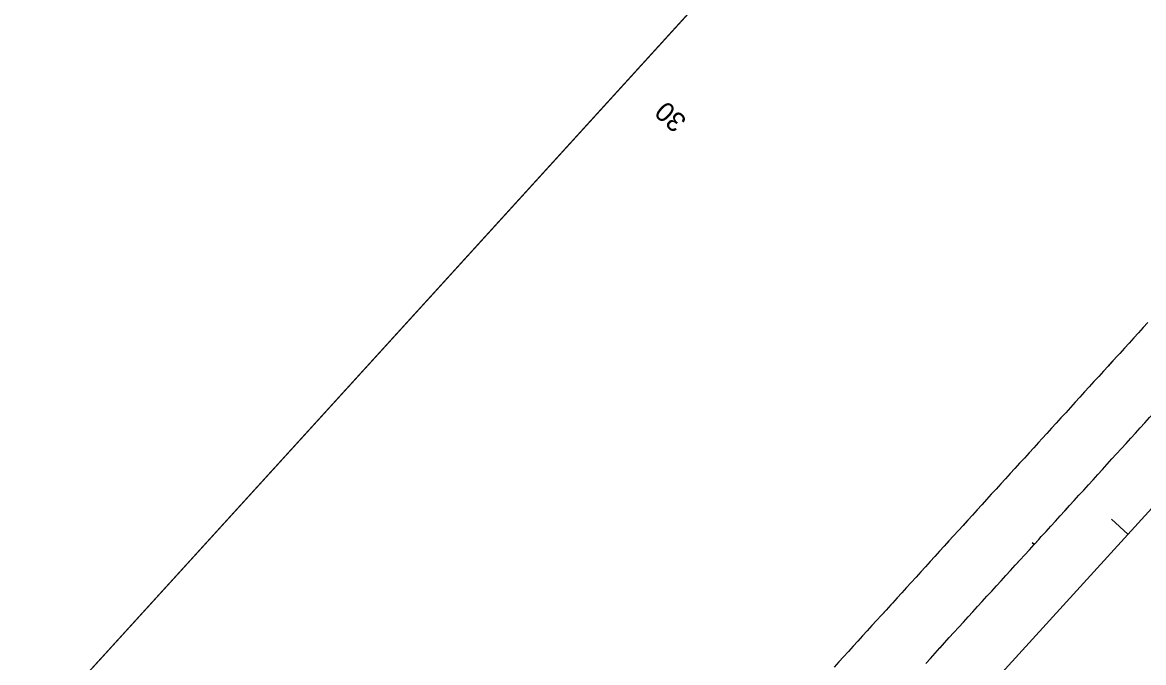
# Model space of a CAD drawing. Extents: x 1807040 to 1808827, y 913493 to 915218.
# Drawn here: x 1807609.2 to 1808009.9, y 914007.6 to 914236.2 of the extents above; entities that cross this region are included whole.
import ezdxf

# ---------------------------------------------------------------- set-up
doc = ezdxf.new("R2010")
doc.units = 0
for name, color, linetype in [('Old_Level_18', 7, 'Continuous'), ('Prop EOT', 7, 'Continuous'), ('Prop Horizontal Alignment Tick Label', 7, 'Continuous'), ('Prop Horizontal Alignment Tick Large', 7, 'Continuous'), ('Scratch_Level_0', 7, 'Continuous'), ('Scratch_Level_1', 7, 'Continuous'), ('Scratch_Level_3', 7, 'Continuous')]:
    doc.layers.add(name, color=color, linetype=linetype)

msp = doc.modelspace()

# ---------------------------------------------------------------- linework, layer by layer
at = {"layer": 'Old_Level_18'}
msp.add_line((1808438.77, 914888.63), (1807428.35, 913780.01), dxfattribs=at)
at = {"layer": 'Prop EOT'}
for points in [[(1808011.43, 914129.13), (1808009.75, 914127.29), (1808008.06, 914125.44), (1808006.38, 914123.59), (1808004.7, 914121.75), (1808003.01, 914119.9), (1808001.33, 914118.05), (1808000.55, 914117.2), (1807998.87, 914115.36), (1807997.18, 914113.51), (1807995.5, 914111.66), (1807993.82, 914109.81), (1807992.13, 914107.96), (1807990.45, 914106.11), (1807988.77, 914104.26), (1807987.08, 914102.42), (1807985.4, 914100.57), (1807983.72, 914098.72), (1807982.04, 914096.87), (1807980.35, 914095.02), (1807978.67, 914093.17), (1807976.99, 914091.32), (1807975.3, 914089.48), (1807973.62, 914087.63), (1807972.3, 914086.18), (1807970.62, 914084.33), (1807968.93, 914082.48), (1807967.25, 914080.64), (1807965.56, 914078.79), (1807963.88, 914076.94), (1807962.19, 914075.1), (1807960.51, 914073.25), (1807958.82, 914071.4), (1807957.14, 914069.56), (1807955.45, 914067.71), (1807953.76, 914065.86), (1807952.08, 914064.01), (1807950.4, 914062.16), (1807948.72, 914060.31), (1807947.04, 914058.46), (1807945.35, 914056.61), (1807943.67, 914054.76), (1807941.99, 914052.91), (1807940.31, 914051.06), (1807938.62, 914049.21), (1807936.94, 914047.36), (1807935.26, 914045.51), (1807933.58, 914043.66), (1807931.9, 914041.81), (1807930.21, 914039.97), (1807928.53, 914038.12), (1807926.85, 914036.27), (1807925.17, 914034.42), (1807923.49, 914032.57), (1807921.8, 914030.72), (1807920.12, 914028.87), (1807919.52, 914028.2), (1807917.83, 914026.35), (1807916.15, 914024.51), (1807914.46, 914022.66), (1807912.78, 914020.81), (1807911.09, 914018.97), (1807909.41, 914017.12), (1807907.72, 914015.27), (1807906.04, 914013.43), (1807904.35, 914011.58), (1807902.66, 914009.73), (1807900.98, 914007.89), (1807899.29, 914006.04)], [(1807931.99, 914007.28), (1807933.68, 914009.13), (1807935.36, 914010.98), (1807937.05, 914012.83), (1807938.73, 914014.67), (1807940.42, 914016.52), (1807942.1, 914018.37), (1807943.79, 914020.21), (1807945.47, 914022.06), (1807947.16, 914023.91), (1807948.84, 914025.76), (1807950.52, 914027.6), (1807952.21, 914029.45), (1807953.89, 914031.3), (1807955.58, 914033.14), (1807957.26, 914034.99), (1807958.95, 914036.84), (1807960.63, 914038.69), (1807962.32, 914040.53), (1807964, 914042.38), (1807965.69, 914044.23), (1807967.37, 914046.08), (1807969.05, 914047.92), (1807970.74, 914049.77), (1807972.42, 914051.62), (1807973.31, 914052.59), (1807975, 914054.44), (1807976.68, 914056.29), (1807978.36, 914058.14), (1807980.04, 914059.99), (1807981.73, 914061.84), (1807983.41, 914063.69), (1807985.09, 914065.54), (1807986.77, 914067.39), (1807988.46, 914069.24), (1807990.14, 914071.08), (1807991.82, 914072.93), (1807993.5, 914074.78), (1807995.19, 914076.63), (1807996.87, 914078.48), (1807998.55, 914080.33), (1808000.23, 914082.18), (1808001.92, 914084.03), (1808003.6, 914085.88), (1808005.28, 914087.73), (1808006.96, 914089.58), (1808008.65, 914091.42), (1808010.33, 914093.27)]]:
    msp.add_lwpolyline(points, dxfattribs=at)
at = {"layer": 'Prop Horizontal Alignment Tick Large'}
msp.add_line((1808004.25, 914053.49), (1807998.34, 914058.88), dxfattribs=at)
at = {"layer": 'Scratch_Level_0'}
for p, q in [((1807995.5, 914111.66), (1807993.82, 914109.81)), ((1807997.18, 914113.51), (1807995.5, 914111.66)), ((1807997.33, 914113.67), (1807997.18, 914113.51)), ((1807992.13, 914107.96), (1807990.45, 914106.11)), ((1807993.82, 914109.81), (1807992.13, 914107.96)), ((1807985.4, 914100.57), (1807983.72, 914098.72)), ((1807987.08, 914102.42), (1807985.4, 914100.57)), ((1807983.72, 914098.72), (1807982.04, 914096.87)), ((1807976.99, 914091.32), (1807975.3, 914089.48)), ((1807978.67, 914093.17), (1807976.99, 914091.32)), ((1807975.3, 914089.48), (1807973.62, 914087.63)), ((1808003.6, 914085.88), (1808005.28, 914087.73)), ((1807970.62, 914084.33), (1807968.93, 914082.48)), ((1807967.25, 914080.64), (1807965.56, 914078.79)), ((1807968.93, 914082.48), (1807967.25, 914080.64)), ((1807996.87, 914078.48), (1807998.55, 914080.33)), ((1807998.55, 914080.33), (1808000.23, 914082.18)), ((1807962.19, 914075.1), (1807960.51, 914073.25)), ((1807963.88, 914076.94), (1807962.19, 914075.1)), ((1807965.56, 914078.79), (1807963.88, 914076.94)), ((1807993.5, 914074.78), (1807995.19, 914076.63)), ((1807995.19, 914076.63), (1807996.87, 914078.48)), ((1807958.82, 914071.4), (1807957.14, 914069.56)), ((1807960.51, 914073.25), (1807958.82, 914071.4)), ((1807988.46, 914069.24), (1807990.14, 914071.08)), ((1807990.14, 914071.08), (1807991.82, 914072.93)), ((1807991.82, 914072.93), (1807993.5, 914074.78)), ((1807957.14, 914069.56), (1807956.95, 914069.35)), ((1807986.77, 914067.39), (1807988.46, 914069.24)), ((1807952.15, 914064.08), (1807952.08, 914064.01)), ((1807953.76, 914065.86), (1807952.15, 914064.08)), ((1807982.03, 914062.17), (1807983.41, 914063.69)), ((1807981.73, 914061.84), (1807982.03, 914062.17)), ((1807943.67, 914054.76), (1807941.99, 914052.91)), ((1807975, 914054.44), (1807976.68, 914056.29)), ((1807976.68, 914056.29), (1807978.36, 914058.14)), ((1807940.31, 914051.06), (1807939.75, 914050.46)), ((1807941.99, 914052.91), (1807940.31, 914051.06)), ((1807971.01, 914050.07), (1807972.42, 914051.62)), ((1807972.42, 914051.62), (1807973.31, 914052.59)), ((1807973.31, 914052.59), (1807975, 914054.44)), ((1807939.75, 914050.46), (1807938.62, 914049.21)), ((1807970.75, 914049.78), (1807970.04, 914050.33)), ((1807970.04, 914050.33), (1807971.01, 914050.07)), ((1807964.48, 914042.91), (1807965.69, 914044.23)), ((1807921.8, 914030.72), (1807920.12, 914028.87)), ((1807919.52, 914028.2), (1807917.83, 914026.35)), ((1807920.12, 914028.87), (1807919.52, 914028.2)), ((1807917.83, 914026.35), (1807916.66, 914025.07)), ((1807911.09, 914018.97), (1807909.57, 914017.31)), ((1807912.78, 914020.81), (1807911.09, 914018.97)), ((1807914.46, 914022.66), (1807912.78, 914020.81)), ((1807943.79, 914020.21), (1807943.86, 914020.3)), ((1807909.57, 914017.31), (1807909.41, 914017.12)), ((1807904.35, 914011.58), (1807902.66, 914009.73)), ((1807937.05, 914012.83), (1807937.13, 914012.91)), ((1807900.98, 914007.89), (1807899.29, 914006.04)), ((1807902.66, 914009.73), (1807900.98, 914007.89)), ((1807931.99, 914007.28), (1807933.68, 914009.13))]:
    msp.add_line(p, q, dxfattribs=at)
for points in [[(1808011.43, 914129.13), (1808009.75, 914127.29), (1808008.06, 914125.44)], [(1808008.06, 914125.44), (1808006.38, 914123.59), (1808004.7, 914121.75), (1808003.01, 914119.9), (1808001.33, 914118.05), (1808000.55, 914117.2)], [(1808000.55, 914117.2), (1807998.87, 914115.36), (1807997.33, 914113.67)], [(1807990.45, 914106.11), (1807988.77, 914104.26), (1807987.08, 914102.42)], [(1807982.04, 914096.87), (1807980.35, 914095.02), (1807978.67, 914093.17)], [(1808008.65, 914091.42), (1808010.33, 914093.27), (1808012.01, 914095.12), (1808013.69, 914096.97)], [(1808005.28, 914087.73), (1808006.96, 914089.58), (1808008.65, 914091.42)], [(1807973.62, 914087.63), (1807972.3, 914086.18), (1807970.62, 914084.33)], [(1808000.23, 914082.18), (1808001.92, 914084.03), (1808003.6, 914085.88)], [(1807956.95, 914069.35), (1807955.45, 914067.71), (1807953.76, 914065.86)], [(1807983.41, 914063.69), (1807985.09, 914065.54), (1807986.77, 914067.39)], [(1807952.08, 914064.01), (1807950.4, 914062.16), (1807948.72, 914060.31)], [(1807948.72, 914060.31), (1807947.04, 914058.46), (1807945.89, 914057.2)], [(1807978.36, 914058.14), (1807980.04, 914059.99), (1807981.73, 914061.84)], [(1807945.89, 914057.2), (1807945.35, 914056.61), (1807943.67, 914054.76)], [(1807938.62, 914049.21), (1807936.94, 914047.36), (1807935.26, 914045.51), (1807933.58, 914043.66)], [(1807965.69, 914044.23), (1807967.37, 914046.08), (1807969.05, 914047.92), (1807970.74, 914049.77), (1807970.75, 914049.78)], [(1807933.58, 914043.66), (1807931.9, 914041.81), (1807930.21, 914039.97), (1807928.53, 914038.12), (1807926.85, 914036.27)], [(1807962.32, 914040.53), (1807964, 914042.38), (1807964.48, 914042.91)], [(1807957.26, 914034.99), (1807958.95, 914036.84), (1807960.63, 914038.69), (1807962.32, 914040.53)], [(1807926.85, 914036.27), (1807925.17, 914034.42), (1807923.49, 914032.57), (1807921.8, 914030.72)], [(1807953.89, 914031.3), (1807955.58, 914033.14), (1807957.26, 914034.99)], [(1807947.16, 914023.91), (1807948.84, 914025.76), (1807950.52, 914027.6), (1807952.21, 914029.45), (1807953.89, 914031.3)], [(1807916.66, 914025.07), (1807916.15, 914024.51), (1807914.46, 914022.66)], [(1807943.86, 914020.3), (1807945.47, 914022.06), (1807947.16, 914023.91)], [(1807937.13, 914012.91), (1807938.73, 914014.67), (1807940.42, 914016.52), (1807942.1, 914018.37), (1807943.79, 914020.21)], [(1807909.41, 914017.12), (1807907.72, 914015.27), (1807906.04, 914013.43), (1807904.35, 914011.58)], [(1807933.68, 914009.13), (1807935.36, 914010.98), (1807937.05, 914012.83)]]:
    msp.add_lwpolyline(points, dxfattribs=at)
at = {"layer": 'Scratch_Level_1'}
for points in [[(1807040.33, 914133.66), (1807040.33, 914133.66), (1807428.35, 913780.01), (1808256.27, 914688.39), (1807868.25, 915042.04)], [(1807489.01, 913846.57), (1807877.03, 913492.93), (1808826.79, 914534.98), (1808438.77, 914888.63)]]:
    msp.add_lwpolyline(points, close=True, dxfattribs=at)
at = {"layer": 'Scratch_Level_3'}
msp.add_line((1807667.44, 913683.95), (1808610.51, 914718.66), dxfattribs=at)

# ---------------------------------------------------------------- texts
at = {"layer": 'Prop Horizontal Alignment Tick Label'}
msp.add_text('30', height=7, rotation=137.6532, dxfattribs=at).set_placement((1807846.97, 914201.57))

doc.saveas('drawing.dxf')
